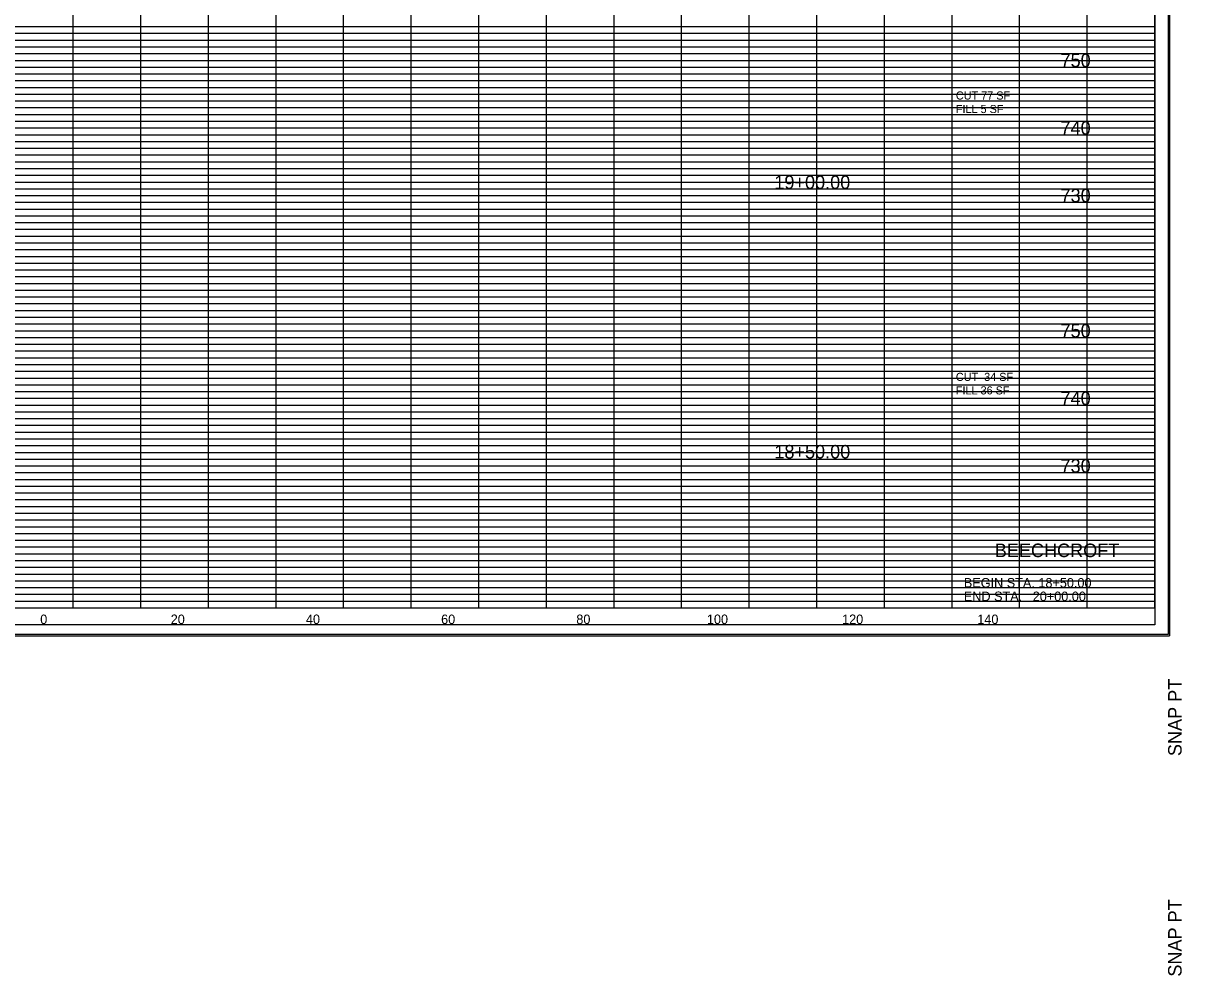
# Model space of a CAD drawing. Extents: x -200 to 1704, y -325 to 2307.
# Drawn here: x 1152.6 to 1324, y 2025.5 to 2166.5 of the extents above; entities that cross this region are included whole.
import ezdxf

# ---------------------------------------------------------------- set-up
doc = ezdxf.new("R2010")
doc.units = 0
for name, color, linetype in [('DESIGN - SHEET - Corner Text', 7, 'Continuous'), ('DESIGN - SHEET - Light Grid', 7, 'Continuous'), ('DESIGN - SHEET - Linework', 7, 'Continuous'), ('DESIGN - SHEET - Plot Shape', 7, 'Continuous'), ('DESIGN - TYPICAL - Text', 7, 'Continuous')]:
    doc.layers.add(name, color=color, linetype=linetype)

msp = doc.modelspace()

# ---------------------------------------------------------------- linework, layer by layer
at = {"layer": 'DESIGN - SHEET - Light Grid'}
for p, q in [((1080, 2166), (1160, 2166)), ((1080, 2165), (1160, 2165)), ((1160, 2166), (1240, 2166)), ((1160, 2165), (1240, 2165)), ((1240, 2166), (1320, 2166)), ((1240, 2165), (1320, 2165)), ((1080, 2164), (1160, 2164)), ((1160, 2164), (1240, 2164)), ((1240, 2164), (1320, 2164)), ((1080, 2163), (1160, 2163)), ((1080, 2162), (1160, 2162)), ((1160, 2163), (1240, 2163)), ((1160, 2162), (1240, 2162)), ((1240, 2163), (1320, 2163)), ((1240, 2162), (1320, 2162)), ((1080, 2161), (1160, 2161)), ((1160, 2161), (1240, 2161)), ((1240, 2161), (1320, 2161)), ((1080, 2159), (1160, 2159)), ((1160, 2159), (1240, 2159)), ((1240, 2159), (1320, 2159)), ((1080, 2158), (1160, 2158)), ((1080, 2157), (1160, 2157)), ((1160, 2158), (1240, 2158)), ((1160, 2157), (1240, 2157)), ((1240, 2158), (1320, 2158)), ((1240, 2157), (1320, 2157)), ((1080, 2156), (1160, 2156)), ((1080, 2155), (1160, 2155)), ((1160, 2156), (1240, 2156)), ((1160, 2155), (1240, 2155)), ((1240, 2156), (1320, 2156)), ((1240, 2155), (1320, 2155)), ((1080, 2154), (1160, 2154)), ((1080, 2153), (1160, 2153)), ((1160, 2154), (1240, 2154)), ((1160, 2153), (1240, 2153)), ((1240, 2154), (1320, 2154)), ((1240, 2153), (1320, 2153)), ((1080, 2152), (1160, 2152)), ((1160, 2152), (1240, 2152)), ((1240, 2152), (1320, 2152)), ((1080, 2151), (1160, 2151)), ((1160, 2151), (1240, 2151)), ((1240, 2151), (1320, 2151)), ((1080, 2149), (1160, 2149)), ((1080, 2148), (1160, 2148)), ((1160, 2149), (1240, 2149)), ((1160, 2148), (1240, 2148)), ((1240, 2149), (1320, 2149)), ((1240, 2148), (1320, 2148)), ((1080, 2147), (1160, 2147)), ((1160, 2147), (1240, 2147)), ((1240, 2147), (1320, 2147)), ((1080, 2146), (1160, 2146)), ((1080, 2145), (1160, 2145)), ((1160, 2146), (1240, 2146)), ((1160, 2145), (1240, 2145)), ((1240, 2146), (1320, 2146)), ((1240, 2145), (1320, 2145)), ((1080, 2144), (1160, 2144)), ((1080, 2143), (1160, 2143)), ((1160, 2144), (1240, 2144)), ((1160, 2143), (1240, 2143)), ((1240, 2144), (1320, 2144)), ((1240, 2143), (1320, 2143)), ((1080, 2142), (1160, 2142)), ((1080, 2141), (1160, 2141)), ((1160, 2142), (1240, 2142)), ((1160, 2141), (1240, 2141)), ((1240, 2142), (1320, 2142)), ((1240, 2141), (1320, 2141)), ((1080, 2139), (1160, 2139)), ((1080, 2138), (1160, 2138)), ((1160, 2139), (1240, 2139)), ((1160, 2138), (1240, 2138)), ((1240, 2139), (1320, 2139)), ((1240, 2138), (1320, 2138)), ((1080, 2137), (1160, 2137)), ((1080, 2136), (1160, 2136)), ((1160, 2137), (1240, 2137)), ((1160, 2136), (1240, 2136)), ((1240, 2137), (1320, 2137)), ((1240, 2136), (1320, 2136)), ((1080, 2135), (1160, 2135)), ((1160, 2135), (1240, 2135)), ((1240, 2135), (1320, 2135)), ((1080, 2134), (1160, 2134)), ((1080, 2133), (1160, 2133)), ((1160, 2134), (1240, 2134)), ((1160, 2133), (1240, 2133)), ((1240, 2134), (1320, 2134)), ((1240, 2133), (1320, 2133)), ((1080, 2132), (1160, 2132)), ((1080, 2131), (1160, 2131)), ((1160, 2132), (1240, 2132)), ((1160, 2131), (1240, 2131)), ((1240, 2132), (1320, 2132)), ((1240, 2131), (1320, 2131)), ((1080, 2129), (1160, 2129)), ((1160, 2129), (1240, 2129)), ((1240, 2129), (1320, 2129)), ((1080, 2128), (1160, 2128)), ((1160, 2128), (1240, 2128)), ((1240, 2128), (1320, 2128)), ((1080, 2127), (1160, 2127)), ((1080, 2126), (1160, 2126)), ((1160, 2127), (1240, 2127)), ((1160, 2126), (1240, 2126)), ((1240, 2127), (1320, 2127)), ((1240, 2126), (1320, 2126)), ((1080, 2125), (1160, 2125)), ((1080, 2124), (1160, 2124)), ((1160, 2125), (1240, 2125)), ((1160, 2124), (1240, 2124)), ((1240, 2125), (1320, 2125)), ((1240, 2124), (1320, 2124)), ((1080, 2123), (1160, 2123)), ((1160, 2123), (1240, 2123)), ((1240, 2123), (1320, 2123)), ((1080, 2122), (1160, 2122)), ((1080, 2121), (1160, 2121)), ((1160, 2122), (1240, 2122)), ((1160, 2121), (1240, 2121)), ((1240, 2122), (1320, 2122)), ((1240, 2121), (1320, 2121)), ((1080, 2119), (1160, 2119)), ((1160, 2119), (1240, 2119)), ((1240, 2119), (1320, 2119)), ((1080, 2118), (1160, 2118)), ((1080, 2117), (1160, 2117)), ((1160, 2118), (1240, 2118)), ((1160, 2117), (1240, 2117)), ((1240, 2118), (1320, 2118)), ((1240, 2117), (1320, 2117)), ((1080, 2116), (1160, 2116)), ((1160, 2116), (1240, 2116)), ((1240, 2116), (1320, 2116)), ((1080, 2115), (1160, 2115)), ((1080, 2114), (1160, 2114)), ((1160, 2115), (1240, 2115)), ((1160, 2114), (1240, 2114)), ((1240, 2115), (1320, 2115)), ((1240, 2114), (1320, 2114)), ((1080, 2113), (1160, 2113)), ((1080, 2112), (1160, 2112)), ((1160, 2113), (1240, 2113)), ((1160, 2112), (1240, 2112)), ((1240, 2113), (1320, 2113)), ((1240, 2112), (1320, 2112)), ((1080, 2111), (1160, 2111)), ((1160, 2111), (1240, 2111)), ((1240, 2111), (1320, 2111)), ((1080, 2109), (1160, 2109)), ((1160, 2109), (1240, 2109)), ((1240, 2109), (1320, 2109)), ((1080, 2108), (1160, 2108)), ((1080, 2107), (1160, 2107)), ((1160, 2108), (1240, 2108)), ((1160, 2107), (1240, 2107)), ((1240, 2108), (1320, 2108)), ((1240, 2107), (1320, 2107)), ((1080, 2106), (1160, 2106)), ((1080, 2105), (1160, 2105)), ((1160, 2106), (1240, 2106)), ((1160, 2105), (1240, 2105)), ((1240, 2106), (1320, 2106)), ((1240, 2105), (1320, 2105)), ((1080, 2104), (1160, 2104)), ((1160, 2104), (1240, 2104)), ((1240, 2104), (1320, 2104)), ((1080, 2103), (1160, 2103)), ((1080, 2102), (1160, 2102)), ((1160, 2103), (1240, 2103)), ((1160, 2102), (1240, 2102)), ((1240, 2103), (1320, 2103)), ((1240, 2102), (1320, 2102)), ((1080, 2101), (1160, 2101)), ((1160, 2101), (1240, 2101)), ((1240, 2101), (1320, 2101)), ((1080, 2099), (1160, 2099)), ((1160, 2099), (1240, 2099)), ((1240, 2099), (1320, 2099)), ((1080, 2098), (1160, 2098)), ((1080, 2097), (1160, 2097)), ((1160, 2098), (1240, 2098)), ((1160, 2097), (1240, 2097)), ((1240, 2098), (1320, 2098)), ((1240, 2097), (1320, 2097)), ((1080, 2096), (1160, 2096)), ((1080, 2095), (1160, 2095)), ((1160, 2096), (1240, 2096)), ((1160, 2095), (1240, 2095)), ((1240, 2096), (1320, 2096)), ((1240, 2095), (1320, 2095)), ((1080, 2094), (1160, 2094)), ((1080, 2093), (1160, 2093)), ((1160, 2094), (1240, 2094)), ((1160, 2093), (1240, 2093)), ((1240, 2094), (1320, 2094)), ((1240, 2093), (1320, 2093)), ((1080, 2092), (1160, 2092)), ((1160, 2092), (1240, 2092)), ((1240, 2092), (1320, 2092)), ((1080, 2091), (1160, 2091)), ((1160, 2091), (1240, 2091)), ((1240, 2091), (1320, 2091)), ((1080, 2089), (1160, 2089)), ((1080, 2088), (1160, 2088)), ((1160, 2089), (1240, 2089)), ((1160, 2088), (1240, 2088)), ((1240, 2089), (1320, 2089)), ((1240, 2088), (1320, 2088)), ((1080, 2087), (1160, 2087)), ((1160, 2087), (1240, 2087)), ((1240, 2087), (1320, 2087)), ((1080, 2086), (1160, 2086)), ((1080, 2085), (1160, 2085)), ((1160, 2086), (1240, 2086)), ((1160, 2085), (1240, 2085)), ((1240, 2086), (1320, 2086)), ((1240, 2085), (1320, 2085)), ((1080, 2084), (1160, 2084)), ((1080, 2083), (1160, 2083)), ((1160, 2084), (1240, 2084)), ((1160, 2083), (1240, 2083)), ((1240, 2084), (1320, 2084)), ((1240, 2083), (1320, 2083)), ((1080, 2082), (1160, 2082)), ((1080, 2081), (1160, 2081)), ((1160, 2082), (1240, 2082)), ((1160, 2081), (1240, 2081)), ((1240, 2082), (1320, 2082)), ((1240, 2081), (1320, 2081))]:
    msp.add_line(p, q, dxfattribs=at)
at = {"layer": 'DESIGN - SHEET - Linework'}
for p, q in [((1322.17, 2294.14), (1322.17, 2075.86)), ((1160, 2080), (1160, 2290)), ((1170, 2080), (1170, 2290)), ((1180, 2080), (1180, 2290)), ((1190, 2080), (1190, 2290)), ((1200, 2080), (1200, 2290)), ((1210, 2080), (1210, 2290)), ((1220, 2080), (1220, 2290)), ((1230, 2080), (1230, 2290)), ((1240, 2080), (1240, 2290)), ((1250, 2080), (1250, 2290)), ((1260, 2080), (1260, 2290)), ((1270, 2080), (1270, 2290)), ((1280, 2080), (1280, 2280)), ((1290, 2080), (1290, 2280)), ((1300, 2080), (1300, 2280)), ((1310, 2080), (1310, 2280)), ((1000, 2160), (1320, 2160)), ((1000, 2150), (1320, 2150)), ((1000, 2140), (1320, 2140)), ((1000, 2130), (1320, 2130)), ((1000, 2120), (1320, 2120)), ((1000, 2110), (1320, 2110)), ((1000, 2100), (1320, 2100)), ((1000, 2090), (1320, 2090)), ((981.77, 2075.86), (1322.17, 2075.86))]:
    msp.add_line(p, q, dxfattribs=at)
msp.add_lwpolyline([(1000, 2290), (1000, 2080), (1320, 2080), (1320, 2290), (1000, 2290)], dxfattribs=at)
at = {"layer": 'DESIGN - SHEET - Plot Shape'}
for points in [[(981.97, 2293.94), (1321.97, 2293.94), (1321.97, 2076.06), (981.97, 2076.06)], [(991.5, 2290), (1320, 2290), (1320, 2077.5), (991.5, 2077.5)]]:
    msp.add_lwpolyline(points, close=True, dxfattribs=at)

# ---------------------------------------------------------------- texts
at = {"layer": 'DESIGN - SHEET - Corner Text'}
for s, height, p in [('BEECHCROFT ', 2, (1296.33, 2087.5)), ('BEGIN STA. 18+50.00', 1.4, (1291.75, 2083)), ('END STA.   20+00.00', 1.4, (1291.75, 2081))]:
    msp.add_text(s, height=height, dxfattribs=at).set_placement(p)
for s, p in [('SNAP PT  ', (1323.97, 2058.06)), ('  SNAP PT', (1323.97, 2023.94))]:
    msp.add_text(s, height=2, rotation=90, dxfattribs=at).set_placement(p)
at = {"layer": 'DESIGN - TYPICAL - Text'}
for s, height, p in [('     750     ', 2, (1302.34, 2160)), ('CUT 77 SF', 1.2, (1290.57, 2155.2)), ('FILL 5 SF', 1.2, (1290.57, 2153.2)), ('     740     ', 2, (1302.34, 2150)), ('     19+00.00     ', 2, (1260, 2141.96)), ('     730     ', 2, (1302.34, 2140)), ('     750     ', 2, (1302.34, 2120)), ('CUT  34 SF', 1.2, (1290.57, 2113.57)), ('FILL 36 SF', 1.2, (1290.57, 2111.57)), ('     740     ', 2, (1302.34, 2110)), ('     18+50.00     ', 2, (1260, 2102.09)), ('     730     ', 2, (1302.34, 2100)), ('     0     ', 1.4, (1152.51, 2077.6)), ('     20     ', 1.4, (1171.82, 2077.6)), ('     40     ', 1.4, (1191.82, 2077.6)), ('     60     ', 1.4, (1211.82, 2077.6)), ('     80     ', 1.4, (1231.82, 2077.6)), ('     100     ', 1.4, (1251.14, 2077.6)), ('     120     ', 1.4, (1271.14, 2077.6)), ('     140     ', 1.4, (1291.14, 2077.6))]:
    msp.add_text(s, height=height, dxfattribs=at).set_placement(p)

doc.saveas('drawing.dxf')
